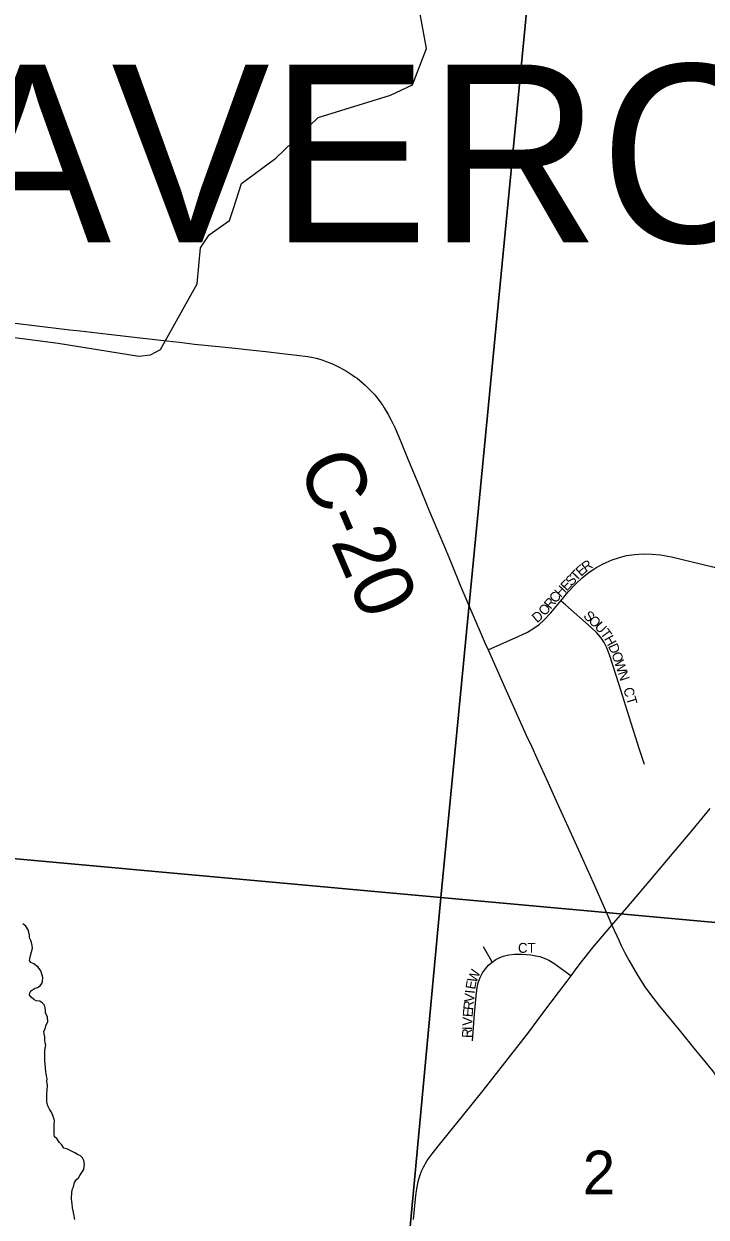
# Model space of a CAD drawing. Extents: x 1410790 to 1770854, y 448063 to 770588.
# Drawn here: x 1552911 to 1556366, y 631210 to 637246 of the extents above; entities that cross this region are included whole.
import ezdxf

# ---------------------------------------------------------------- set-up
doc = ezdxf.new("R2010")
doc.units = 0
for name, color, linetype in [('GM_X_County_Road', 7, 'Continuous'), ('GM_X_County_Road_Text', 7, 'Continuous'), ('GM_X_Minor_River', 7, 'Continuous'), ('GM_X_Section', 7, 'Continuous'), ('GM_X_Section_Text', 7, 'Continuous'), ('GM_X_Township_Road', 7, 'Continuous'), ('GM_X_Township_Subdivision', 7, 'Continuous'), ('GM_X_Township_Subdivision_Text', 7, 'Continuous'), ('GM_X_Township_Text', 7, 'Continuous')]:
    doc.layers.add(name, color=color, linetype=linetype)

msp = doc.modelspace()

# ---------------------------------------------------------------- linework, layer by layer
at = {"layer": 'GM_X_County_Road'}
for points in [[(1552838.6, 635734.8), (1552949.4, 635722.2), (1553144.8, 635699), (1553197, 635693), (1553340.4, 635676.7), (1553500.2, 635658.2), (1553636, 635643.1), (1553699.4, 635635.2), (1553775.8, 635626.2), (1553897.3, 635613.6), (1553980.7, 635604.9), (1554054.9, 635597.5), (1554136.5, 635588.8), (1554220.2, 635579.3), (1554294.4, 635570.6), (1554349.5, 635562.8), (1554376.5, 635558), (1554391.5, 635554.3), (1554409.9, 635549.3), (1554425.1, 635544.5), (1554442.4, 635538.5), (1554461.5, 635531.1), (1554480.7, 635522.8), (1554504.1, 635511.6), (1554530.6, 635497.2), (1554544.9, 635489), (1554560.9, 635479), (1554576.1, 635469), (1554587.4, 635461.3), (1554598.7, 635453), (1554613.1, 635441.4), (1554640.1, 635417.9), (1554663.5, 635395.3), (1554687.8, 635369.1), (1554710.5, 635341.4), (1554719.8, 635328.8), (1554729.3, 635315), (1554736.4, 635304.1), (1554746.7, 635287.2), (1554756.4, 635270.6), (1554771.7, 635241.8), (1554791.3, 635200.5), (1554818.2, 635137.3), (1554857.7, 635040), (1554910.8, 634912.9), (1554960.9, 634791.6), (1555041.2, 634601.2), (1555074.9, 634519.4), (1555124.3, 634397.8), (1555174.4, 634280), (1555247.7, 634111.5), (1555261.9, 634079.5)], [(1555261.9, 634079.5), (1555268.9, 634063.5), (1555339.6, 633904.7), (1555455.6, 633647.5), (1555483.3, 633588.1), (1555509.7, 633531.7), (1555564.8, 633410), (1555598.8, 633334.7), (1555717.6, 633071.5), (1555794.4, 632901.8), (1555863.9, 632745.5), (1555888.6, 632687)], [(1555888.6, 632687), (1555925.9, 632606.8), (1555936.6, 632583.7), (1555946.2, 632563.7), (1555954.8, 632546.4), (1555974.8, 632509.1), (1556019.2, 632433.1), (1556056.1, 632375.4), (1556084.5, 632335.5), (1556130.7, 632276.5), (1556234.7, 632150.4), (1556311.2, 632056.2)], [(1556311.2, 632056.2), (1556335.9, 632025.8), (1556397.7, 631949.1), (1556446.4, 631882.8), (1556490.8, 631813.5), (1556553.7, 631705.7), (1556727, 631400.3), (1556735.3, 631386.2)]]:
    msp.add_lwpolyline(points, dxfattribs=at)
at = {"layer": 'GM_X_Minor_River'}
for points in [[(1552642.7, 635688.7), (1553084.8, 635631.2), (1553494.3, 635564.7), (1553552.6, 635571.5), (1553603.2, 635598.5), (1553788.3, 635931.4), (1553805.9, 636113.5), (1553849.3, 636178.7), (1553953, 636250.8), (1553972.3, 636312.5), (1554012.8, 636437.9), (1554187.8, 636566.6), (1554402.4, 636772.7), (1554767.4, 636885.5), (1554878.7, 636937.3), (1554950.5, 637122.2), (1554912.5, 637323.4)], [(1552945.5, 632532.4), (1552955.8, 632570.4), (1552954, 632584.4), (1552950.1, 632598.5), (1552946.1, 632608.5), (1552940.3, 632622.6), (1552940.4, 632636.6), (1552936.5, 632650.7), (1552932.6, 632662.8), (1552920.7, 632680.9), (1552906.8, 632693)], [(1553169, 631198), (1553165.2, 631224.1), (1553161.3, 631242.2), (1553157.4, 631256.2), (1553155.6, 631276.3), (1553153.7, 631288.3), (1553151.8, 631302.4), (1553151.9, 631314.4), (1553154, 631326.4), (1553154.1, 631336.4), (1553158.2, 631352.4), (1553162.3, 631362.4), (1553168.5, 631384.4), (1553178.6, 631400.3), (1553188.6, 631408.2), (1553194.8, 631420.2), (1553215, 631450.1), (1553217.1, 631466.1), (1553219.2, 631478.1), (1553215.4, 631496.2), (1553207.5, 631510.3), (1553197.6, 631520.4), (1553183.6, 631526.5), (1553169.7, 631534.7), (1553149.7, 631544.8), (1553129.8, 631555), (1553113.8, 631559.2), (1553102, 631577.3), (1553090, 631589.4), (1553078.2, 631607.6), (1553066.2, 631615.7), (1553064.4, 631629.7), (1553064.5, 631651.8), (1553064.7, 631669.8), (1553064.8, 631681.8), (1553066.9, 631695.8), (1553065, 631705.9), (1553059.1, 631717.9), (1553053.2, 631738), (1553041.4, 631756.2), (1553033.5, 631772.2), (1553029.6, 631784.3), (1553027.7, 631794.3), (1553027.8, 631814.4), (1553028, 631836.4), (1553030.1, 631850.4), (1553030.3, 631876.5), (1553028.5, 631896.5), (1553028.6, 631910.5), (1553026.7, 631924.6), (1553022.9, 631944.7), (1553021, 631962.7), (1553019.2, 631984.8), (1553017.3, 631996.8), (1553017.4, 632010.8), (1553017.6, 632036.9), (1553017.7, 632048.9), (1553019.8, 632064.9), (1553021.9, 632078.9), (1553020, 632090.9), (1553018.1, 632105), (1553018.3, 632121), (1553014.4, 632137.1), (1553012.5, 632149.1), (1553018.6, 632163.1), (1553024.8, 632183.1), (1553032.9, 632197), (1553031.1, 632223.1), (1553021.2, 632241.2), (1553021.4, 632255.2), (1553019.5, 632267.3), (1553015.6, 632281.3), (1553003.7, 632293.5), (1552991.7, 632301.6), (1552973.7, 632303.7), (1552961.8, 632309.9), (1552947.8, 632322), (1552939.9, 632332.1), (1552942, 632344.1), (1552946.1, 632354.1), (1552968.2, 632367.9), (1552980.3, 632371.8), (1552994.3, 632379.7), (1553002.4, 632391.7), (1553006.5, 632401.6), (1553006.7, 632421.7), (1553004.8, 632433.7), (1552996.9, 632455.8), (1552983.1, 632474), (1552961.2, 632490.2), (1552947.3, 632498.3), (1552939.3, 632508.4), (1552945.5, 632532.4)]]:
    msp.add_lwpolyline(points, dxfattribs=at)
at = {"layer": 'GM_X_Section'}
for points in [[(1550230.3, 638666.5), (1555538.6, 638162.6), (1555022.2, 632826.4), (1549719.6, 633308.3)], [(1549719.6, 633308.3), (1555022.2, 632826.4), (1554631.8, 628627.9), (1554620.8, 627934.3), (1554618.6, 627918.3), (1554618, 627882.4), (1554617.3, 627836.4), (1554614.8, 627806.4), (1554624.4, 627780.3), (1554668.6, 627671.6), (1554687.9, 627625.3), (1554689.4, 627591.3), (1554684.9, 627563.4), (1554674.5, 627535.6), (1554652.2, 627519.9), (1554620, 627502.5), (1554585.9, 627497), (1554498, 627498.4), (1554418, 627499.6), (1554372, 627500.4), (1554330.2, 627507), (1554298.4, 627519.5), (1554266.6, 627536), (1549189.3, 627980.4)]]:
    msp.add_lwpolyline(points, close=True, dxfattribs=at)
for points in [[(1558212.7, 632536), (1555022.2, 632826.4), (1555538.6, 638162.6)], [(1554631.8, 628627.9), (1555022.2, 632826.4), (1558212.7, 632536)]]:
    msp.add_lwpolyline(points, dxfattribs=at)
at = {"layer": 'GM_X_Township_Road'}
for points in [[(1555888.6, 632687), (1555965.3, 632774.5), (1556077.7, 632907.2), (1556210.8, 633065.3), (1556293, 633163.4), (1556387.4, 633276.9)], [(1555682.6, 632430.8), (1555705.2, 632461.1), (1555729, 632492.4), (1555793.9, 632574.8), (1555888.6, 632687)], [(1554883.6, 631196.9), (1554896.6, 631319.7), (1554900.7, 631352), (1554907.9, 631390.2), (1554915.8, 631418.2), (1554924.7, 631442.3), (1554934.2, 631462.8), (1554953.4, 631496.4), (1554968.4, 631517), (1554978.7, 631529), (1555009.5, 631568.9), (1555133.2, 631720.3), (1555237.8, 631850.5), (1555346.8, 631989.9), (1555468, 632144.9), (1555534.7, 632234.4), (1555623.1, 632352.1), (1555662.2, 632403.5), (1555682.6, 632430.8)]]:
    msp.add_lwpolyline(points, dxfattribs=at)
at = {"layer": 'GM_X_Township_Subdivision'}
for points in [[(1555630.5, 634327.9), (1555668.3, 634372.7), (1555706.2, 634414), (1555737.7, 634443.3), (1555774.1, 634471.9), (1555807.4, 634493.7), (1555845.2, 634514.1), (1555890.6, 634534.2), (1555928.1, 634547.2), (1555963.6, 634555.9), (1556002.9, 634561.8), (1556049.1, 634564.9), (1556092.2, 634564.1), (1556134.9, 634559.4), (1556190, 634549.2), (1556400.6, 634499.5), (1556470.4, 634480), (1556510.9, 634465.9), (1556550.2, 634448.3), (1556584.8, 634428.6), (1556620, 634403.7), (1556655.5, 634374), (1556683.9, 634346.3), (1556699.6, 634328.6)], [(1555261.9, 634079.5), (1555296.7, 634095), (1555413.7, 634146.7), (1555460.9, 634168.8), (1555494.5, 634188.3), (1555520.7, 634207), (1555544.6, 634228.7), (1555579.4, 634267.4), (1555630.5, 634327.9)], [(1556054.4, 633499.9), (1556029.6, 633574.7), (1555976.6, 633740.3), (1555925.1, 633903), (1555877.8, 634049.9), (1555862.6, 634090.2), (1555849.2, 634117.1), (1555832.6, 634142.2), (1555813.2, 634165.2), (1555784.7, 634192.8), (1555653.8, 634307.5), (1555630.5, 634327.9)], [(1555282.3, 632499.9), (1555272, 632518.4), (1555239, 632577.5)], [(1555282.3, 632499.9), (1555301.2, 632512.9), (1555318.1, 632521.8), (1555339.1, 632529.4), (1555367.3, 632536.2), (1555396.1, 632539.5), (1555433.2, 632540.1), (1555456.6, 632538.7), (1555478.9, 632536.3), (1555504.4, 632532.2), (1555523.4, 632527.3), (1555546.7, 632520.4), (1555570.1, 632510.1), (1555594.9, 632495), (1555650.3, 632454.4), (1555682.6, 632430.8)], [(1555183.3, 632102.2), (1555193.9, 632236.8), (1555202, 632328.5), (1555206.5, 632370.4), (1555212.3, 632395.4), (1555222.5, 632422.5), (1555234.5, 632445.2), (1555249, 632466.4), (1555263.6, 632483.4), (1555282.3, 632499.9)]]:
    msp.add_lwpolyline(points, dxfattribs=at)

# ---------------------------------------------------------------- texts
at = {"layer": 'GM_X_County_Road_Text'}
msp.add_text('C-20', height=300, rotation=293.24316, dxfattribs=at).set_placement((1554296.4, 635015.8))
at = {"layer": 'GM_X_Section_Text'}
msp.add_text('2', height=221, rotation=0.00001, dxfattribs=at).set_placement((1555741.2, 631324.7))
at = {"layer": 'GM_X_Township_Subdivision_Text'}
for s, rotation, p in [('E', 41.69479, (1555732.5, 634448.4)), ('R', 35.44168, (1555757.7, 634471)), ('S', 45.94679, (1555684.2, 634398.7)), ('T', 45.61813, (1555708.6, 634423.9)), ('H', 46.45295, (1555629.4, 634341.6)), ('E', 45.94679, (1555659.7, 634373.4)), ('R', 50.36441, (1555578.8, 634281.9)), ('C', 48.95345, (1555603.8, 634312.1)), ('D', 40.29541, (1555510, 634213.1)), ('O', 49.64404, (1555549.8, 634247.8)), ('S', 316.449, (1555741.1, 634246.8)), ('O', 316.43712, (1555766.6, 634222.6)), ('U', 314.52088, (1555798.1, 634192.6)), ('T', 306.38899, (1555827.8, 634162.6)), ('H', 298.90176, (1555847.7, 634135.7)), ('D', 293.92477, (1555868.5, 634098.2)), ('O', 289.24364, (1555885.9, 634059)), ('W', 287.98298, (1555900.3, 634017.8)), ('N', 287.93037, (1555918, 633963.4)), ('CT', 286.39442, (1555946.1, 633881.8)), ('CT', 0.00001, (1555413.4, 632546.6)), ('W', 68.5014, (1555201.8, 632391.1)), ('E', 79.75623, (1555196.2, 632358.9)), ('V', 84.17632, (1555189.7, 632294.3)), ('I', 84.17632, (1555194.1, 632338.1)), ('R', 84.38123, (1555185.8, 632254.9)), ('V', 87.89755, (1555181.9, 632176.6)), ('E', 86.20046, (1555183.5, 632220.2)), ('R', 87.91125, (1555179.6, 632115.1)), ('I', 87.90154, (1555181.1, 632154.7))]:
    msp.add_text(s, height=50, rotation=rotation, dxfattribs=at).set_placement(p)
at = {"layer": 'GM_X_Township_Text'}
msp.add_text('BEAVERCREEK', height=900, rotation=0.00001, dxfattribs=at).set_placement((1550945.8, 636140.2))

doc.saveas('drawing.dxf')
